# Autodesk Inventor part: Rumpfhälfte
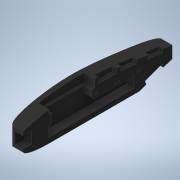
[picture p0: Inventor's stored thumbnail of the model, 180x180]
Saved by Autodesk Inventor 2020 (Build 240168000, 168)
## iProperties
Part Number: Rumpfhälfte
Material: GEDA Polyamid schwarz
Document SubType Name: Modeling
Designer: Admin
Density: 1.14 g/cm^3
Appearance: GEDA Plastik schwarz A
Mass: 2170.29 g
Surface Area: 2080.02 cm^2
Volume: 1903.76 cm^3
Gewicht: 2,170 kg
G_L: 0
G_H: 0
G_B: 0
InventorVersion: 2019.4
VAULT_Status: in Bearbeitung
Revision: -
Max. Breite: 0
Max. Höhe: 0
Max. Länge: 0
Max. Abmessungen: 0 x 0 x 0
Author: Admin
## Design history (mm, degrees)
sketch "Skizze1"
  geometry: L1 (0, 285)-(-57, 285); L2 (-57, 285)-(-57, -285); L3 (-57, -285)-(0, -285); L4 (0, -285)-(0, 285); L5 (-40, 285)-(-57, 285); L6 (-57, 285)-(-57, 175); L7 (-36, -285)-(-57, -285); L8 (-57, -285)-(-57, -175); 2 further points
  constraints: 8 end point, 4 point on line, 3 coincident, 2 collinear, 2 parallel, 1 horizontal, 1 midpoint, 1 perpendicular, 6 other
  dimensions: "d0" = 57 distance of L1.start L1.end; "d1" = 570 distance of L1.end L2.end; "d2" = 40 distance of L1.start L5.start; "d3" = 110 distance of L1.end L6.end; "d5" = 110 distance of L7.end L8.end; "d100" = 36 distance from line of L4 L7.start
extrude "Extrusion1" new body sketch "Skizze1" distance "d6" = 127; taper "d7" = 0 deg
sketch "Skizze2"
  geometry: L1 (-90, 0)-(-139.333, 200); L2 (-139.333, 200)-(-139.333, 250); L3 (-139.333, 250)-(-90, 570); L4 (0, 570)-(0, 0) reference; L5 (-90, 0)-(-137, 0); L6 (-137, 0)-(-137, 570); L7 (-137, 570)-(-90, 570); L8 (-45, 570)-(0, 445); L9 (0, 570)-(0, 0) reference; L10 (-20, 0)-(0, 20); L11 (0, 20)-(0, 110); L12 (-46.491, 0)-(10, 0); L13 (10, 0)-(10, 570); L14 (10, 570)-(-45, 570); L15 (0, 110)-(0, 445); L16 (0, 0)-(-127, 0) reference; 7 further points
  constraints: 16 end point, 4 horizontal, 4 point on line, 3 perpendicular, 2 collinear, 1 parallel, 1 vertical, 1 vertical alignment, 8 other
  dimensions: "d8" = 90 distance from line of L4 L1.start; "d13" = 10 dimension on L6; "d15" = 45 distance from line of L4 L8.start; "d16" = 20 distance from line of L4 L10.start; "d19" = 10 distance between parallel lines of L4 L13; "d22" = 20 distance from line of L16 L10.end; "d23" = 125 dimension on L8.end; "d24" = 200 distance from line of L5 L1.end; "d25" = 250 distance from line of L16 L2.end; "d26" = 110 distance from line of L16 L11.end
extrude "Extrusion3" cut sketch "Skizze2" distance "d27" = 120; taper "d28" = 0 deg
fillet "Rundung1" dims "d29" = 15
fillet "Rundung2" dims "d30" = 1
extrude "Extrusion4" cut sketch "Skizze1" extent not by distance; stored distance "d31" = 120; taper "d32" = 0 deg
sketch "Skizze3"
  geometry: L1 (-27.484, -110)-(-78.236, -110) reference; L2 (-75, -110)-(-30, -110); L3 (-30, -110)-(-30, -75); L4 (-30, -75)-(-75, -75); L5 (-75, -75)-(-75, -110); L6 (0, 335)-(0, 0) reference; L7 (0, 335)-(-44.762, 459.339) reference; L8 (-23.31, 355.465)-(-47.02, 421.327); L9 (-32.907, 426.408)-(-47.02, 421.327); L10 (-23.31, 355.465)-(-9.196, 360.546); L11 (-5.4, 350)-(0, 335) reference; L12 (-9.196, 360.546)-(-32.907, 426.408); L13 (-127, -10)-(-20, -10); L14 (-20, -10)-(-20, 165); L15 (-127, 165)-(-127, -10); L16 (-20, 165)-(-60, 165); L17 (-60, 165)-(-60, 315); L18 (-20, 315)-(-20, 165); L19 (-127, 177)-(-102, 177); L20 (-102, 177)-(-102, 247); L21 (-102, 247)-(-127, 247); L22 (-127, 247)-(-127, 177); L23 (-45.703, 460)-(-89.142, 460) reference; L24 (-60, 315)-(-20, 315); L25 (-95, -10)-(-55, -10); L26 (-55, -10)-(-55, -2); L27 (-55, -2)-(-95, 2); L28 (-95, 2)-(-95, -10); L29 (-60, 165)-(-60, 153); L30 (-60, 153)-(-95, 153); L31 (-95, 153)-(-95, 165); L32 (-20, 165)-(-60, 165); L33 (-95, 165)-(-127, 165); L34 (-117.65, 264.922)-(-102.65, 263); L35 (-102.65, 263)-(-95.026, 322.514); L36 (-95.026, 322.514)-(-110.026, 324.435); L37 (-103.659, 369.358)-(-89.261, 367.514); L38 (-89.261, 367.514)-(-82.146, 423.06); L39 (-82.146, 423.06)-(-95.397, 424.757); L40 (-83, 237)-(-68, 237); L41 (-68, 237)-(-68, 262); L42 (-68, 262)-(-83, 262); L43 (-83, 262)-(-83, 237); C1 r 7 at (-75, 172); C2 r 7 at (-70, 332); 7 further points
  constraints: 76 end point, 13 parallel, 11 perpendicular, 9 horizontal, 6 point on line, 5 collinear, 2 centre point, 1 equal radius, 1 tangent, 1 vertical, 5 other
  dimensions: "d35" = 35 distance of L4.end L2.start; "d37" = 15 distance between parallel lines of L7 L8; "d38" = 70 distance between parallel lines of L10 L9; "d39" = 35 distance from line of L7.end L9; "d40" = 20 distance between parallel lines of L6 L14; "d47" = 25 distance between parallel lines of L22 L20; "d48" = 150 distance between parallel lines of L16 L24; "d49" = 70 distance of L21.end L19.start; "d50" = 100 distance between parallel lines of L1 L13; "d51" = 175 distance of L15.start L13.start; "d56" = 14 diameter of C1; "d59" = 128 distance from line of L23 C2.centre; "d97" = 45 distance of L3.end L4.end; "d98" = 30 distance between parallel lines of L6 L3; "d99" = 40 distance of L17.end L18.start; "d102" = 8 distance of L25.end L26.end; "d103" = 12 distance of L27.end L25.start; "d104" = 40 distance between parallel lines of L26 L28; "d105" = 35 distance between parallel lines of L14 L26; "d108" = 12 distance of L30.end L31.end; "d109" = 15 distance from line of L17 C1.centre; "d110" = 12 distance between parallel lines of L33 L19; "d111" = 70 distance from line of L6 C2.centre; "d112" = 160 vertical distance of C1.centre C2.centre; "d113" = 60 distance between parallel lines of L36 L34; "d114" = 15 horizontal distance of L34.start L34.end; "d115" = 16 vertical distance of L20.end L34.end; "d116" = 45 vertical distance of L37.end L35.end; "d117" = 56 distance between parallel lines of L39 L37; "d118" = 15 distance of L41.end L42.end; "d119" = 25 distance of L42.end L40.start; "d120" = 65 distance from line of C1.centre L40
extrude "Extrusion5" cut sketch "Skizze3" distance "d52" = 30; taper "d53" = 0 deg
extrude "Extrusion6" cut sketch "Skizze3" distance "d54" = 15; taper "d55" = 0 deg
extrude "Extrusion7" cut sketch "Skizze3" extent not by distance; stored distance "d60" = 20; taper "d61" = 0 deg
fillet "Rundung3" dims "d62" = 15
sketch "Skizze4"
  geometry: L1 (45.703, 460)-(89.142, 460) reference; L2 (71.2, 404.5)-(60.5, 404.5); L3 (73, 389.5)-(59.7, 389.5); L4 (75.1, 374.5)-(58.7, 374.5); L5 (77.8, 359.5)-(58.3, 359.5); L6 (79.5, 344.5)-(57.7, 344.5); L7 (81.9, 329.5)-(57.2, 329.5); L8 (83.6, 314.5)-(56.7, 314.5); L9 (85.7, 299.5)-(55.7, 299.5); L10 (87.8, 284.5)-(55.1, 284.5); L11 (89.5, 269.5)-(54.8, 269.5); L12 (91.7, 254.5)-(54.8, 254.5); L13 (92.6, 239.5)-(54.1, 239.5); L14 (94.1, 224.5)-(54.1, 224.5); L15 (94.9, 209.5)-(53.7, 209.5); L16 (96, 194.5)-(53.5, 194.5); L17 (96.2, 179.5)-(53.5, 179.5); L18 (96.2, 164.5)-(53.8, 164.5); L19 (95.5, 149.5)-(53.8, 149.5); L20 (94.7, 134.5)-(54.2, 134.5); L21 (93.1, 119.5)-(54.5, 119.5); L22 (90.2, 104.5)-(55.3, 104.5); L23 (86.7, 89.5)-(57.5, 89.5); L24 (80.3, 74.5)-(58.9, 74.5); L25 (60.5, 403.36)-(70.5, 407); L26 (70.5, 407)-(67.5, 407); L27 (70.5, 407)-(83.6, 314.5); L28 (83.6, 314.5)-(100.2, 212); L29 (100.2, 212)-(100.2, 137); L30 (100.2, 137)-(87.5, 77); L31 (87.5, 77)-(69.5, 60.5); L32 (65.5, 60.5)-(55.5, 67); L33 (55.5, 67)-(52.9, 149.5); L34 (52.9, 149.5)-(52.9, 212); L35 (52.9, 212)-(55.7, 299.5); L36 (55.7, 299.5)-(60.5, 403.36); C1 r 7 at (70, 332) reference; C2 r 7 at (75, 172) reference; A1 r 2.5 centre (67.5, 62) between (69.5, 60.5) and (65.5, 60.5); 2 further points; 1 other entity
  constraints: 50 end point, 7 parallel, 6 horizontal, 3 coincident, 2 point on circle, 1 centre point, 1 horizontal alignment, 1 vertical, 60 other
  dimensions: "d65" = 5 diameter of A1; "d70" = 15 distance between parallel lines of L2 L3 (= d67); "d71" = 15 distance between parallel lines of L3 L4 (= d67); "d72" = 15 distance between parallel lines of L4 L5 (= d67); "d73" = 15 distance between parallel lines of L6 L5 (= d67); "d74" = 15 distance between parallel lines of L7 L6 (= d67); "d75" = 15 distance between parallel lines of L8 L7 (= d67); "d76" = 15 distance between parallel lines of L9 L8 (= d67); "d77" = 15 distance between parallel lines of L9 L10 (= d67); "d78" = 15 distance between parallel lines of L10 L11 (= d67); "d79" = 15 distance between parallel lines of L11 L12 (= d67); "d80" = 15 distance between parallel lines of L12 L13 (= d67); "d81" = 15 distance between parallel lines of L14 L13 (= d67); "d82" = 15 distance between parallel lines of L15 L14 (= d67); "d83" = 15 distance between parallel lines of L16 L15 (= d67); "d84" = 15 distance between parallel lines of L17 L16 (= d67); "d85" = 15 distance between parallel lines of L18 L17 (= d67); "d86" = 15 distance between parallel lines of L19 L18 (= d67); "d88" = 15 distance between parallel lines of L20 L19 (= d67); "d89" = 15 distance between parallel lines of L21 L20 (= d67); "d90" = 15 distance between parallel lines of L22 L21 (= d67); "d91" = 15 distance between parallel lines of L22 L23 (= d67); "d92" = 15 distance between parallel lines of L23 L24 (= d67); "d94" = 1.5 vertical distance of L31.end point (67.5, 62); "d132" = 12.5 distance from line of L24 A1.centre; "d133" = 12.8 dimension on L24.start; "d134" = 19.2 dimension on L23.start; "d135" = 22.7 dimension on L22.start; "d136" = 25.6 dimension on L21.start; "d137" = 27.2 dimension on L20.start; "d138" = 28 dimension on L19.start; "d139" = 28.7 dimension on L18.start; "d140" = 28.7 dimension on L17.start (derived); "d141" = 110 vertical distance of point (67.5, 62) C2.centre; "d142" = 28.5 dimension on L16.start; "d143" = 27.4 dimension on L15.start; "d144" = 26.6 dimension on L14.start; "d145" = 25.1 dimension on L13.start; "d146" = 24.2 dimension on L12.start; "d148" = 20.3 dimension on L10.start; "d149" = 18.2 dimension on L9.start; "d151" = 345 distance of L26.end point (67.5, 62); "d152" = 22 dimension on L11.start; "d153" = 16.1 dimension on L8.start; "d155" = 14.4 dimension on L7.start; "d156" = 12 dimension on L6.start; "d157" = 10.3 dimension on L5.start; "d158" = 7.6 dimension on L4.start; "d159" = 5.5 dimension on L3.start; "d160" = 3.7 dimension on L2.start; "d161" = 10 horizontal distance of L25.start L25.end; "d162" = 70 deg angle to the sketch y axis of L25; "d163" = 3 dimension on L25.end; "d164" = 4 distance from line of L29 L17.start; "d165" = 15 vertical distance of point (67.5, 62) L30.end; "d166" = 75 vertical distance of point (67.5, 62) L29.end; "d167" = 150 vertical distance of point (67.5, 62) L28.end; "d168" = 8.6 dimension on L24.end; "d169" = 10 dimension on L23.end; "d170" = 12.2 dimension on L22.end; "d171" = 13 dimension on L21.end; "d172" = 13.3 dimension on L20.end; "d173" = 13.7 dimension on L19.end; "d174" = 13.7 dimension on L18.end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
extrude "Extrusion8" cut sketch "Skizze4" distance "d95" = 10; taper "d96" = 0 deg
fillet "Rundung4" dims "d121" = 3
sketch "Skizze5"
  geometry: L1 (-95, -10)-(-112.654, -10) reference; L2 (-95, -10)-(-132, -10); L3 (-132, -10)-(-132, 165); L4 (-132, 165)-(-95, 165); L5 (-95, 165)-(-95, -10); 4 further points
  constraints: 8 end point, 2 parallel, 1 horizontal, 1 perpendicular, 1 other
  dimensions: "d122" = 5 distance from line of L3 point (-127, 130)
extrude "Extrusion9" cut sketch "Skizze5" distance "d123" = 10; taper "d124" = 0 deg
node "Volumenkörper1"
feature "耀䁌"
feature "쀀䁀"
other parameters: "Gewicht" = 21.70291 [user parameter], "G_L" = 0 [user parameter], "G_H" = 0 [user parameter], "G_B" = 0 [user parameter], "d67" = 15, "d107" = 12
